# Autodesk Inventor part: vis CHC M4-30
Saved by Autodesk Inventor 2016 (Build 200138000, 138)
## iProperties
Created: 2010-10
Part Number: vis CHC M4-30
Material: Générique
Document SubType Name: Modeling
Designer: Bruno
Density: 1 g/cm^3
Appearance: Par défaut
Author: Bruno
Sending System: SolidWorks 2013
Last Author: christophe
Last Saved: 2014-02-15
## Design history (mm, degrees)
feature "Enlèv. mat.-Extru.1"
node "Solide1"
